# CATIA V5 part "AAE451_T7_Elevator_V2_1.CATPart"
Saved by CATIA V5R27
Part number: Elevator
Bounding box of the stored display mesh (mm): x 0 to 69.698, y -12.436 to 0.05, z 0 to 344.945
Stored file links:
  W:\AAE 451\AAE451_T7_TailAssembly_V2\AAE451_T7_Elevator_V2_1.CATPart
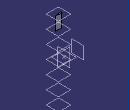
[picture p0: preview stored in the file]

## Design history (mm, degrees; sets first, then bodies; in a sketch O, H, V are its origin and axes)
Set1 "GeometryFromExcel"
  Point1: (1, 0.001, 0)
  Point2: (0.95, 0.0067, 0)
  Point3: (0.9, 0.0121, 0)
  Point4: (0.8, 0.0219, 0)
  Point5: (0.7, 0.0305, 0)
  Point6: (0.6, 0.038, 0)
  Point7: (0.5, 0.0441, 0)
  Point8: (0.4, 0.0484, 0)
  Point9: (0.3, 0.05, 0)
  Point10: (0.25, 0.0495, 0)
  Point11: (0.2, 0.0478, 0)
  Point12: (0.15, 0.0445, 0)
  Point13: (0.1, 0.039, 0)
  Point14: (0.075, 0.035, 0)
  Point15: (0.05, 0.0296, 0)
  Point16: (0.025, 0.0218, 0)
  Point17: (0.0125, 0.0158, 0)
  Point18: (0, 0, 0)
  Point19: (0.0125, -0.0158, 0)
  Point20: (0.025, -0.0218, 0)
  Point21: (0.05, -0.0296, 0)
  Point22: (0.075, -0.035, 0)
  Point23: (0.1, -0.039, 0)
  Point24: (0.15, -0.0445, 0)
  Point25: (0.2, -0.0478, 0)
  Point26: (0.25, -0.0495, 0)
  Point27: (0.3, -0.05, 0)
  Point28: (0.4, -0.0484, 0)
  Point29: (0.5, -0.0441, 0)
  Point30: (0.6, -0.038, 0)
  Point31: (0.7, -0.0305, 0)
  Point32: (0.8, -0.0219, 0)
  Point33: (0.9, -0.0121, 0)
  Point34: (0.95, -0.0067, 0)
  Point35: (1, -0.001, 0)
  Point36: (1, 0.001, 0)
  Point37: (0.95, 0.0067, 0)
  Point38: (0.9, 0.0121, 0)
  Point39: (0.8, 0.0219, 0)
  Point40: (0.7, 0.0305, 0)
  Point41: (0.6, 0.038, 0)
  Point42: (0.5, 0.0441, 0)
  Point43: (0.4, 0.0484, 0)
  Point44: (0.3, 0.05, 0)
  Point45: (0.25, 0.0495, 0)
  Point46: (0.2, 0.0478, 0)
  Point47: (0.15, 0.0445, 0)
  Point48: (0.1, 0.039, 0)
  Point49: (0.075, 0.035, 0)
  Point50: (0.05, 0.0296, 0)
  Point51: (0.025, 0.0218, 0)
  Point52: (0.0125, 0.0158, 0)
  Point53: (0, 0, 0)
  Point54: (0.0125, -0.0158, 0)
  Point55: (0.025, -0.0218, 0)
  Point56: (0.05, -0.0296, 0)
  Point57: (0.075, -0.035, 0)
  Point58: (0.1, -0.039, 0)
  Point59: (0.15, -0.0445, 0)
  Point60: (0.2, -0.0478, 0)
  Point61: (0.25, -0.0495, 0)
  Point62: (0.3, -0.05, 0)
  Point63: (0.4, -0.0484, 0)
  Point64: (0.5, -0.0441, 0)
  Point65: (0.6, -0.038, 0)
  Point66: (0.7, -0.0305, 0)
  Point67: (0.8, -0.0219, 0)
  Point68: (0.9, -0.0121, 0)
  Point69: (0.95, -0.0067, 0)
  Point70: (1, -0.001, 0)
  Curve1: Elements (Point36; Point37; Point38; Point39; Point40; Point41; Point42; Point43; Point44; Point45; Point46; Point47; Point48; Point49; Point50; Point51; Point52; Point53; Point54; Point55; Point56; Point57; Point58; Point59; Point60; Point61; Point62; Point63; Point64; Point65; Point66; Point67; Point68; Point69; Point70)
  Sketch1 on xy-plane, origin (0, 0, 0), H (1, 0, 0), V (0, 1, 0)
    projected curve E1 from edge of Curve1
    point P1 (1, 0.0011)
    line L1 (1, 0.0011) -> (1, -0.001)
    point P3 (1, 0.001)
    point P4 (1, -0.001)
    reference projected point E2 (1, 0.001) from Point1
    reference projected point E3 (1, -0.001) from Point35
    coincidence: P3 E2, P4 E3, P1 P3
Body1 (main body)
  Pad1: profile Sketch1, direction (0, 0, 1), length 1.5215, mirrored extent
  Scaling1: Reference Point40, Ratio 230, ToTransfor Pad1
  Plane1: type Offset, RefPlane yz-plane, Offset 120, reversed
  Sketch2 on xy-plane, origin (0, 0, 0), H (1, 0, 0), V (0, 1, 0)
    reference projected line E1 (69.6979, -7.2245) -> (69.698, -6.7499) from edge [face of Pad1 from Sketch1.L1 | end face of Pad1]
    line L1 (13.6994, -1.0636) -> (13.6965, -12.9194)
    projected curve E2 from edge [face of Pad1 from Sketch1.E1 | end face of Pad1]
    projected curve E3 from edge [face of Pad1 from Sketch1.E1 | end face of Pad1]
    distance E1 L1 = 56
  Pocket1: profile Sketch2, direction (0, 0, -1), through (limit type 3), opposite side through (limit type 3)
  Fillet1: radius 5, on edge [face of Pad1 from Sketch1.E1 | face of Pocket1 from Sketch2.L1]; edge [face of Pocket1 from Sketch2.L1 | face of Pad1 from Sketch1.E1]
  Sketch3 on zx-plane, origin (0, 0, 0), H (-1, 0, 0), V (0, 0, 1)
    line L1 (-135.4649, -344.945) -> (50.2623, -344.945)
    line L2 (50.2623, -344.945) -> (50.2623, -349.945)
    line L3 (50.2623, -349.945) -> (-135.4649, -349.945)
    line L4 (-135.4649, -349.945) -> (-135.4649, -344.945)
    line L5 (-146.4826, 349.945) -> (56.5582, 349.945)
    line L6 (56.5582, 349.945) -> (56.5582, 344.945)
    line L7 (56.5582, 344.945) -> (-146.4826, 344.945)
    line L8 (-146.4826, 344.945) -> (-146.4826, 349.945)
    reference projected line E1 (-69.7, 349.945) -> (160.3, 349.945) from edge [face of Pad1 from Sketch1.E1 | end face of Pad1]
    reference projected line E2 (-69.7, -349.945) -> (160.3, -349.945) from edge [start face of Pad1 | face of Pad1 from Sketch1.E1]
    distance L7 L5 = 5
    horizontal: L1 H, L3 H, L5 H, L7 H
    vertical: L2 V, L4 V, L6 V, L8 V
    coincidence: L5 E1, L3 E2
    symmetry: L7 L1 H
  Pocket2: profile Sketch3, direction (0, -1, 0), through (limit type 3)
  Sketch4 on face of Pocket1 from Sketch2.L1, origin (13.6996, -0.0033, 0), H (-0.0002, -1, 0), V (0, 0, 1)
    line L1 (6.4867, 8) -> (7.4867, 8)
    line L2 (7.4867, 8) -> (7.4867, -8)
    line L3 (7.4867, -8) -> (6.4867, -8)
    line L4 (6.4867, -8) -> (6.4867, 8)
    construction line L5 (6.9867, 7.1913) -> (6.9867, -6.7162)
    reference projected line E1 (1.5418, 344.945) -> (1.5418, -344.945) from edge [face of Pad1 from Sketch1.E1 | face of Fillet1]
    reference projected line E2 (12.4317, 344.945) -> (12.4317, -344.945) from edge [face of Fillet1 | face of Pad1 from Sketch1.E1]
    distance L4 L2 = 1
    distance L1 L3 = 16
    horizontal: L1 H, L3 H
    vertical: L2 V, L4 V
    symmetry: L3 L1 H, L4 L2 L5, E1 E2 L5
  Pocket3: profile Sketch4, direction (1, -0.0002, 0), length 13.7
  RectPattern1: of Pocket3, direction 1 instances 2, spacing 230, along zx-plane
  Mirror1: of RectPattern1, about xy-plane
  Plane2: type Offset, RefPlane face of Pocket2 from Sketch3.L7, Offset 0, reversed
  Plane3: type Offset, RefPlane face of Pocket2 from Sketch3.L1, Offset 0, reversed
  Plane4: type Offset, RefPlane Plane3, Offset 114.98
  Plane5: type Offset, RefPlane Plane4, Offset 114.98
  Plane6: type Offset, RefPlane Plane5, Offset 114.98
  Plane7: type Offset, RefPlane Plane6, Offset 114.98
  Plane8: type Offset, RefPlane Plane7, Offset 114.98
  Split1: SplitPlane Plane8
